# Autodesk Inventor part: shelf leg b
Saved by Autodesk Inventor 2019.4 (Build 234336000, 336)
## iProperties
Created: 2020-09
Part Number: shelf leg b
Material: Generic
Document SubType Name: Modeling
Designer: Administrator
Density: 1 g/cm^3
Appearance: Default
Title: shelf leg b
Author: Administrator
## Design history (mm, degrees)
feature "Body1"
body "Solid1"
